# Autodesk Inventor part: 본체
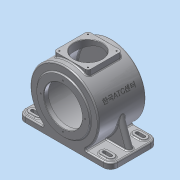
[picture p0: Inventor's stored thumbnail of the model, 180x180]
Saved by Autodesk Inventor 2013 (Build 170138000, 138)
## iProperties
Created: 2015-06
Part Number: 본체
Material: 알루미늄 6061
Document SubType Name: Modeling
Designer: Administrator
Mass: 3275.78 g
Surface Area: 2302.33 cm^2
Volume: 1208.77 cm^3
Density: 2.71 g/cm^3
Author: Administrator
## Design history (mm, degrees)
sketch "스케치1" dims "d0" = 170
  geometry: L1 (0, 0)-(0, -85); L2 (85, 0)-(0, 0); L3 (0, 0)-(77.036, 35.923); C1 r 77 at (0, 0); C2 r 65 at (0, 0); C3 r 31 at (0, 0); 2 further points
  constraints: 6 end point, 4 coincident, 3 centre point, 1 horizontal alignment, 1 perpendicular, 1 vertical, 2 other
  dimensions: "d1" = 154 diameter of C1; "d2" = 130 diameter of C2; "d29" = 62 diameter of C3; "d90" = 85 distance of L2.end L3.end; "d91" = 25 deg angle of L3 L2
extrude "돌출1" new body sketch "스케치1" stored distance "d3" = 118; taper "d4" = 0 deg
node "작업 평면1"
sketch "스케치2"
  geometry: L1 (-97, 59)-(97, 59); L2 (115, 41)-(115, -41); L3 (97, -59)-(-97, -59); L4 (-115, -41)-(-115, 41); L5 (-115, 59)-(115, -59); L6 (115, 59)-(-115, -59); L7 (97, -32)-(81, -32); L8 (97, -50)-(81, -50); L9 (97, -45)-(81, -45); L10 (97, -37)-(81, -37); L11 (115, 0)-(-115, 0); L12 (0, -59)-(0, 59); L13 (-115, 0)-(115, 0); L14 (-97, -50)-(-81, -50); L15 (-97, -32)-(-81, -32); L16 (-97, -37)-(-81, -37); L17 (-97, -45)-(-81, -45); L18 (97, 32)-(81, 32); L19 (97, 37)-(81, 37); L20 (97, 50)-(81, 50); L21 (97, 45)-(81, 45); L22 (-97, 50)-(-81, 50); L23 (-97, 45)-(-81, 45); L24 (-97, 37)-(-81, 37); L25 (-97, 32)-(-81, 32); A1 r 18 centre (97, -41) between (97, -59) and (115, -41); A2 r 18 centre (97, 41) between (115, 41) and (97, 59); A3 r 18 centre (-97, 41) between (-97, 59) and (-115, 41); A4 r 18 centre (-97, -41) between (-115, -41) and (-97, -59); A5 r 9 centre (97, -41) between (97, -50) and (97, -32); A6 r 9 centre (81, -41) between (81, -32) and (81, -50); A7 r 4 centre (97, -41) between (97, -45) and (97, -37); A8 r 4 centre (81, -41) between (81, -37) and (81, -45); A9 r 9 centre (-97, -41) between (-97, -32) and (-97, -50); A10 r 9 centre (-81, -41) between (-81, -50) and (-81, -32); A11 r 4 centre (-97, -41) between (-97, -37) and (-97, -45); A12 r 4 centre (-81, -41) between (-81, -45) and (-81, -37); A13 r 9 centre (81, 41) between (81, 50) and (81, 32); A14 r 4 centre (97, 41) between (97, 37) and (97, 45); A15 r 9 centre (97, 41) between (97, 32) and (97, 50); A16 r 4 centre (81, 41) between (81, 45) and (81, 37); A17 r 9 centre (-81, 41) between (-81, 32) and (-81, 50); A18 r 4 centre (-81, 41) between (-81, 37) and (-81, 45); A19 r 4 centre (-97, 41) between (-97, 45) and (-97, 37); A20 r 9 centre (-97, 41) between (-97, 50) and (-97, 32); 3 further points
  constraints: 50 end point, 40 point on circle, 40 symmetric about line, 20 centre point, 16 tangent, 8 coincident, 8 point on line, 6 midpoint, 3 equal radius, 2 parallel, 1 horizontal, 1 horizontal alignment, 1 perpendicular, 12 other
  dimensions: "d7" = 230 distance of L5.end L6.end; "d8" = 118 distance of L6.start L5.end; "d9" = 18 radius of A1; "d12" = 18 diameter of A5; "d13" = 18 diameter of A6; "d14" = 8 diameter of A7; "d15" = 8 diameter of A8; "d16" = 97 horizontal distance of A7.centre point (0, 0); "d17" = 16 distance of A8.centre A5.centre; "d18" = 41 vertical distance of A5.centre point (0, 0)
extrude "돌출2" join sketch "스케치2" distance "d10" = 14; taper "d11" = 0 deg
sketch "스케치3"
  geometry: L1 (-97, 50)-(-81, 50) reference; L2 (115, -59)-(-115, 59) reference; L3 (-97, 45)-(-81, 45) reference; L4 (-97, 37)-(-81, 37) reference; L5 (-97, 32)-(-81, 32) reference; L6 (-97, -59)-(97, -59) reference; L7 (-115, 41)-(-115, -41) reference; L8 (97, 59)-(-97, 59) reference; L9 (115, -41)-(115, 41) reference; L10 (-97, -37)-(-81, -37) reference; L11 (-97, -45)-(-81, -45) reference; L12 (-115, -59)-(115, 59) reference; L13 (-97, -32)-(-81, -32) reference; L14 (-97, -50)-(-81, -50) reference; L15 (97, 37)-(81, 37) reference; L16 (97, 45)-(81, 45) reference; L17 (97, 50)-(81, 50) reference; L18 (97, 32)-(81, 32) reference; L19 (97, -37)-(81, -37) reference; L20 (97, -45)-(81, -45) reference; L21 (97, -32)-(81, -32) reference; L22 (97, -50)-(81, -50) reference; A1 r 9 centre (-97, 41) between (-97, 50) and (-97, 32) reference; A2 r 9 centre (-81, 41) between (-81, 32) and (-81, 50) reference; A3 r 4 centre (-81, 41) between (-81, 37) and (-81, 45) reference; A4 r 4 centre (-97, 41) between (-97, 45) and (-97, 37) reference; A5 r 18 centre (-97, -41) between (-115, -41) and (-97, -59) reference; A6 r 18 centre (-97, 41) between (-97, 59) and (-115, 41) reference; A7 r 18 centre (97, 41) between (115, 41) and (97, 59) reference; A8 r 18 centre (97, -41) between (97, -59) and (115, -41) reference; A9 r 4 centre (-97, -41) between (-97, -37) and (-97, -45) reference; A10 r 4 centre (-81, -41) between (-81, -45) and (-81, -37) reference; A11 r 9 centre (-97, -41) between (-97, -32) and (-97, -50) reference; A12 r 9 centre (-81, -41) between (-81, -50) and (-81, -32) reference; A13 r 4 centre (81, 41) between (81, 45) and (81, 37) reference; A14 r 9 centre (81, 41) between (81, 50) and (81, 32) reference; A15 r 4 centre (97, 41) between (97, 37) and (97, 45) reference; A16 r 9 centre (97, 41) between (97, 32) and (97, 50) reference; A17 r 4 centre (81, -41) between (81, -37) and (81, -45) reference; A18 r 9 centre (81, -41) between (81, -32) and (81, -50) reference; A19 r 4 centre (97, -41) between (97, -45) and (97, -37) reference; A20 r 9 centre (97, -41) between (97, -50) and (97, -32) reference; 1 further point
  node "투영된 루프1"
extrude "돌출3" join sketch "스케치3" distance "d19" = 3; taper "d20" = 0 deg
extrude "돌출4" cut sketch "스케치3" stored distance "d21" = 3; taper "d22" = 0 deg
extrude "돌출5" join sketch "스케치1" distance "d23" = 62; taper "d25" = 0 deg; dims "d24" = 72, "d26" = 0
extrude "돌출6" cut sketch "스케치1" stored distance "d27" = 102; taper "d28" = 0 deg
hole "구멍1" diameter "d32" = 95; stored, may be unused: countersink angle "d36" = 90 deg, drill point angle "d38" = 0 deg; dims "d30" = 10, "d31" = 10, "d33" = 6, "d34" = 4, "d35" = 2, "d37" = 11
sketch "스케치4"
  geometry: C1 r 31 at (0, 0) reference
extrude "돌출7" join sketch "스케치4" distance "d39" = 3.5; taper "d40" = -25 deg
hole "구멍2" diameter "d43" = 30; stored, may be unused: countersink angle "d47" = 90 deg, drill point angle "d49" = 0 deg; dims "d41" = 10, "d42" = 10, "d44" = 6, "d45" = 47, "d46" = 14, "d48" = 17
node "작업 평면2"
sketch "스케치5"
  geometry: L1 (42.5, -42.5)-(-42.5, -42.5); L2 (-42.5, -42.5)-(-42.5, 42.5); L3 (-42.5, 42.5)-(42.5, 42.5); L4 (42.5, 42.5)-(42.5, -42.5); L5 (42.5, -42.5)-(-42.5, 42.5); L6 (-42.5, -42.5)-(42.5, 42.5); 1 further point
  constraints: 12 end point, 2 midpoint, 2 parallel, 1 horizontal, 1 perpendicular
  dimensions: "d51" = 85 distance of L2.end L3.end; "d52" = 85 distance of L1.end L2.end
extrude "돌출8" join sketch "스케치5" stored distance "d53" = 3.5; taper "d54" = 0 deg
sketch "스케치6"
  geometry: 1 further point
hole "구멍3" sketch "스케치6" at (0, 0) diameter "d55" = 70; stored, may be unused: countersink angle "d59" = 90 deg, drill point angle "d61" = 0 deg; dims "d56" = 6, "d57" = 47, "d58" = 14, "d60" = 17
sketch "스케치7"
  geometry: L1 (-42.5, 42.5)-(42.5, 42.5) reference; L2 (-42.5, -42.5)-(-42.5, 42.5) reference; C1 r 35 at (0, 0) reference; 4 further points
  constraints: 1 horizontal, 1 vertical, 3 other
  dimensions: "d62" = 35.5 horizontal distance of point (-35.5, 35.5) C1.centre; "d63" = 35.5 horizontal distance of point (-35.5, 35.5) C1.centre; "d66" = 71 distance of point (-35.5, 35.5) point (35.5, 35.5); "d69" = 71 distance of point (-35.5, 35.5) point (-35.5, -35.5)
hole "구멍4" sketch "스케치7" at (-35.5, 35.5), (35.5, 35.5), (-35.5, -35.5), (35.5, -35.5) diameter "d72" = 3.242; stored, may be unused: countersink angle "d76" = 90 deg, drill point angle "d78" = 118 deg; dims "d73" = 10, "d74" = 47, "d75" = 14, "d77" = 13
sketch "스케치8"
  geometry: C1 r 47.5 at (0, 0) reference; 1 further point
  constraints: 1 vertical alignment
  dimensions: "d79" = 55 distance of point (0, 55) C1.centre
hole "구멍5" sketch "스케치8" at (0, 55) diameter "d80" = 3.242; stored, may be unused: countersink angle "d84" = 90 deg, drill point angle "d86" = 0 deg; dims "d81" = 15, "d82" = 47, "d83" = 14, "d85" = 15
node "작업 평면3"
sketch "스케치9"
  geometry: 2 further points
  constraints: 1 other
feature "엠보싱1" sketch "스케치9" dims "d0" = 170, "d1" = 154, "d2" = 130, "d10" = 14, "d29" = 62, "d90" = 85, "d91" = 25 deg, "d92" = 0.5, "d93" = 0
chamfer "모따기1" distance "d94" = 1; stored, may be unused: second distance "d95" = 2, angle "d96" = 45 deg
fillet "모깎기1" dims "d97" = 0.3
fillet "모깎기7" dims "d121" = 7
fillet "모깎기8" dims "d122" = 3
sketch "스케치11"
  geometry: L1 (-97, -71)-(-115, -71) reference; L2 (-109, -71)-(-84.87, -4.703); L3 (-115, -85)-(-115, -71) reference; L4 (-109, -71)-(-46.733, -71); A1 r 85 centre (0, 0) between (46.733, -71) and (-46.733, -71) reference; 1 further point
  constraints: 4 end point, 1 perpendicular, 1 point on circle, 1 point on line
  dimensions: "d114" = 6 distance from line of L2.start L3; "d115" = 110 deg angle of L2 L1; "d116" = 85 radius of A1 (derived)
extrude "돌출10" join sketch "스케치11" stored distance "d117" = 15; taper "d118" = 0 deg
fillet "모깎기5" dims "d119" = 7.5
fillet "모깎기6" dims "d120" = 3
fillet "모깎기9" dims "d123" = 3
node "솔리드1"
pattern_circular "원형 패턴1" dims angle "d88" = 360 deg
mirror "대칭2"
other parameters: "d5" = -85, "d50" = 88
